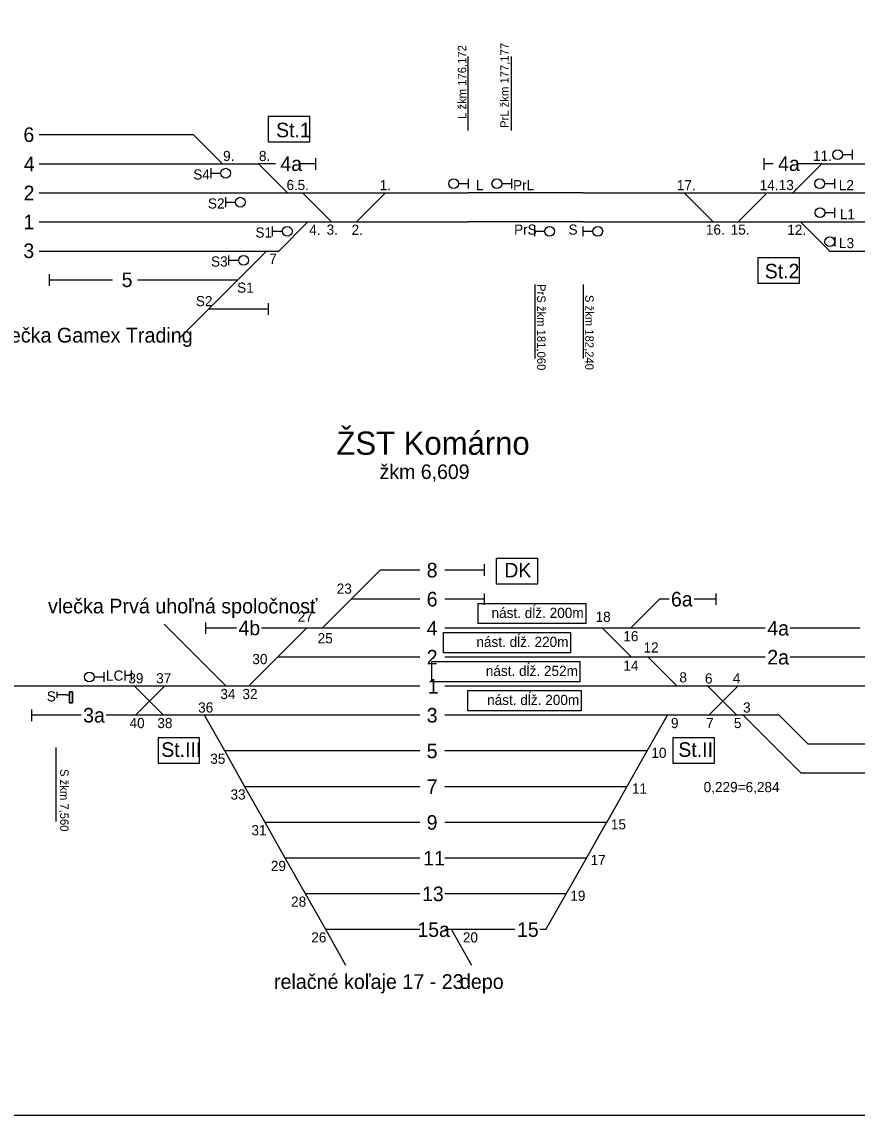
# Model space of a CAD drawing. Extents: x -119 to 851, y -238 to 59.
# Drawn here: x 333.1 to 390.6, y -238 to -162.7 of the extents above; entities that cross this region are included whole.
import ezdxf

# ---------------------------------------------------------------- set-up
doc = ezdxf.new("R2010")
doc.units = 0
for name, color, linetype in [('2', 7, 'Continuous'), ('budova', 7, 'Continuous'), ('Default', 7, 'Continuous'), ('Level 2', 7, 'Continuous'), ('nastupistia', 7, 'Continuous'), ('netlač', 7, 'Continuous'), ('popisky navestidla', 7, 'Continuous'), ('popisky stanic a zastavok', 7, 'Continuous'), ('PU_navestidla', 7, 'Continuous'), ('PU_oznacenie navestidiel', 7, 'Continuous'), ('PU_stan_kolaje', 7, 'Continuous'), ('PU_vlecky', 7, 'Continuous')]:
    doc.layers.add(name, color=color, linetype=linetype)

msp = doc.modelspace()

# ---------------------------------------------------------------- linework, layer by layer
at = {"layer": '2'}
for p, q in [((335.501, -209.067), (335.501, -208.855)), ((335.501, -209.278), (335.501, -209.067)), ((336.123, -209.067), (335.501, -209.067))]:
    msp.add_line(p, q, dxfattribs=at)
for points in [[(336.569, -208.864), (336.359, -208.864), (336.359, -209.61), (336.569, -209.61)], [(336.569, -208.87), (336.359, -208.87), (336.359, -209.61), (336.569, -209.61)]]:
    msp.add_lwpolyline(points, close=True, dxfattribs=at)
at = {"layer": 'budova'}
for points in [[(350.05, -170.981), (352.917, -170.981), (352.917, -169.232), (350.05, -169.232)], [(383.798, -180.699), (386.665, -180.699), (386.665, -178.951), (383.798, -178.951)], [(368.632, -199.668), (365.765, -199.668), (365.765, -201.417), (368.632, -201.417)], [(345.329, -212.023), (342.462, -212.023), (342.462, -213.771), (345.329, -213.771)], [(380.798, -212.023), (377.931, -212.023), (377.931, -213.771), (380.798, -213.771)]]:
    msp.add_lwpolyline(points, close=True, dxfattribs=at)
at = {"layer": 'Default'}
for p, q in [((336.359, -209.61), (336.359, -208.864)), ((336.569, -208.864), (336.569, -209.61)), ((336.569, -209.61), (336.359, -209.61))]:
    msp.add_line(p, q, dxfattribs=at)
msp.add_lwpolyline([(336.123, -209.067), (336.359, -209.067)], dxfattribs=at)
at = {"layer": 'Level 2'}
for p, q in [((344.908, -170.496), (334.273, -170.496)), ((353.342, -172.894), (353.342, -172.095)), ((384.219, -172.894), (384.219, -172.095)), ((334.273, -172.495), (349.377, -172.495)), ((350.55, -172.495), (349.377, -172.495)), ((353.342, -172.495), (352.274, -172.495)), ((384.846, -172.495), (384.219, -172.495)), ((388.2, -172.495), (386.57, -172.495)), ((388.2, -172.495), (409.052, -172.495)), ((334.273, -174.494), (341.172, -174.494)), ((341.172, -174.494), (363.841, -174.494)), ((371.756, -174.494), (377.88, -174.494)), ((377.88, -174.494), (394.077, -174.494)), ((334.273, -176.493), (342.172, -176.493)), ((342.172, -176.493), (360.47, -176.493)), ((360.47, -176.493), (363.841, -176.493)), ((371.756, -176.493), (392.877, -176.493)), ((334.273, -178.492), (350.775, -178.492)), ((388.728, -178.492), (409.052, -178.492)), ((334.986, -180.89), (334.986, -180.091)), ((339.326, -180.491), (334.986, -180.491)), ((347.946, -180.491), (341.049, -180.491)), ((350.081, -182.889), (350.081, -182.09)), ((350.081, -182.49), (345.947, -182.49)), ((364.932, -200.071), (364.932, -200.871)), ((360.51, -200.471), (357.772, -200.471)), ((364.932, -200.471), (362.234, -200.471)), ((360.51, -202.47), (355.773, -202.47)), ((364.932, -202.47), (362.234, -202.47)), ((364.932, -202.07), (364.932, -202.87)), ((377.691, -202.47), (377.013, -202.47)), ((380.887, -202.47), (379.415, -202.47)), ((380.887, -202.07), (380.887, -202.87)), ((345.723, -204.069), (345.723, -204.869)), ((347.864, -204.469), (345.723, -204.469)), ((354.804, -204.469), (349.588, -204.469)), ((360.51, -204.469), (352.688, -204.469)), ((384.302, -204.469), (373.094, -204.469)), ((390.834, -204.469), (386.025, -204.469)), ((360.51, -206.468), (350.689, -206.468)), ((376.239, -206.468), (362.234, -206.468)), ((384.302, -206.468), (376.239, -206.468)), ((392.833, -206.468), (386.025, -206.468)), ((360.51, -208.467), (281.352, -208.467)), ((405.253, -208.467), (362.234, -208.467)), ((333.747, -210.064), (333.747, -210.864)), ((337.159, -210.464), (333.747, -210.464)), ((342.828, -210.464), (338.882, -210.464)), ((360.51, -210.466), (342.83, -210.466)), ((385.268, -210.466), (362.234, -210.466)), ((360.51, -212.925), (347.055, -212.925)), ((376.165, -212.925), (362.234, -212.925)), ((424.601, -212.465), (387.267, -212.465)), ((404.28, -214.464), (386.776, -214.464)), ((360.51, -215.386), (348.447, -215.386)), ((374.769, -215.386), (362.234, -215.386)), ((360.51, -217.847), (349.838, -217.847)), ((373.373, -217.847), (362.234, -217.847)), ((360.51, -220.308), (351.23, -220.308)), ((371.977, -220.308), (362.234, -220.308)), ((360.51, -222.769), (352.621, -222.769)), ((370.581, -222.769), (362.234, -222.769)), ((360.51, -225.23), (354.013, -225.23)), ((362.688, -225.23), (362.234, -225.23)), ((367.056, -225.23), (362.688, -225.23)), ((369.19, -225.23), (368.779, -225.23))]:
    msp.add_line(p, q, dxfattribs=at)
at = {"layer": 'nastupistia'}
for points in [[(371.93, -204.157), (364.516, -204.157), (364.516, -202.772), (371.93, -202.772)], [(370.886, -206.156), (362.127, -206.156), (362.127, -204.771), (370.886, -204.771)], [(371.535, -208.155), (361.33, -208.155), (361.33, -206.77), (371.535, -206.77)], [(371.626, -210.154), (363.819, -210.154), (363.819, -208.769), (371.626, -208.769)]]:
    msp.add_lwpolyline(points, close=True, dxfattribs=at)
at = {"layer": 'netlač'}
for p, q in [((371.756, -174.494), (363.841, -174.494)), ((371.756, -176.493), (363.841, -176.493)), ((373.094, -204.469), (362.234, -204.469))]:
    msp.add_line(p, q, dxfattribs=at)
at = {"layer": 'popisky navestidla'}
for p, q in [((363.841, -170.181), (363.841, -165.091)), ((366.815, -170.181), (366.815, -165.091)), ((368.428, -180.806), (368.428, -185.897)), ((371.756, -180.806), (371.756, -185.897)), ((335.452, -217.779), (335.452, -212.688))]:
    msp.add_line(p, q, dxfattribs=at)
msp.add_lwpolyline([(-118.951, -238.008), (851.049, -238.008), (851.049, 58.992), (-118.951, 58.992)], close=True, dxfattribs=at)
at = {"layer": 'PU_navestidla'}
for p, q in [((390.295, -171.524), (390.295, -172.196)), ((390.295, -171.861), (389.623, -171.861)), ((346.118, -173.466), (346.118, -172.795)), ((346.118, -173.129), (346.79, -173.129)), ((363.841, -173.859), (363.169, -173.859)), ((363.841, -173.522), (363.841, -174.194)), ((366.815, -173.859), (366.143, -173.859)), ((366.815, -173.522), (366.815, -174.194)), ((389.067, -173.859), (388.395, -173.859)), ((389.067, -173.522), (389.067, -174.194)), ((347.13, -175.465), (347.13, -174.794)), ((347.13, -175.128), (347.802, -175.128)), ((389.084, -175.858), (388.412, -175.858)), ((389.084, -175.521), (389.084, -176.193)), ((350.351, -177.464), (350.351, -176.793)), ((368.428, -177.466), (368.428, -176.794)), ((371.756, -177.466), (371.756, -176.794)), ((350.351, -177.127), (351.023, -177.127)), ((368.428, -177.129), (369.1, -177.129)), ((371.756, -177.129), (372.428, -177.129)), ((389.087, -177.52), (389.087, -178.192)), ((347.346, -179.463), (347.346, -178.792)), ((347.346, -179.126), (348.018, -179.126)), ((338.732, -207.495), (338.732, -208.167)), ((338.732, -207.832), (338.06, -207.832))]:
    msp.add_line(p, q, dxfattribs=at)
for centre in [(389.287, -171.86), (347.126, -173.131), (362.833, -173.857), (365.807, -173.857), (388.059, -173.857), (348.138, -175.13), (388.076, -175.856), (351.359, -177.129), (369.436, -177.13), (372.764, -177.13), (388.751, -177.856), (348.354, -179.128), (337.724, -207.831)]:
    msp.add_circle(centre, 0.336, dxfattribs=at)
at = {"layer": 'PU_stan_kolaje'}
for p, q in [((347.946, -180.491), (343.912, -184.525)), ((347.153, -208.467), (342.879, -204.194))]:
    msp.add_line(p, q, dxfattribs=at)
for points in [[(344.908, -170.496), (346.907, -172.495)], [(349.377, -172.495), (351.376, -174.494)], [(388.2, -172.495), (386.201, -174.494)], [(352.42, -174.494), (354.419, -176.493)], [(358.13, -174.494), (356.131, -176.493)], [(378.715, -174.494), (380.714, -176.493)], [(384.424, -174.494), (382.425, -176.493)], [(352.774, -176.493), (350.775, -178.492)], [(386.729, -176.493), (388.726, -178.49)], [(349.945, -178.492), (347.946, -180.491)], [(355.773, -202.47), (357.772, -200.471)], [(353.774, -204.469), (355.773, -202.47)], [(375.014, -204.469), (377.013, -202.47)], [(350.689, -206.468), (352.688, -204.469)], [(375.093, -206.468), (373.094, -204.469)], [(348.69, -208.467), (350.689, -206.468)], [(378.238, -208.467), (376.239, -206.468)], [(342.83, -210.466), (340.831, -208.467)], [(340.912, -210.466), (342.911, -208.467)], [(382.338, -210.466), (380.339, -208.467)], [(380.42, -210.466), (382.419, -208.467)], [(347.055, -212.925), (345.664, -210.464)], [(376.169, -212.927), (377.56, -210.466)], [(384.777, -212.465), (382.778, -210.466)], [(387.267, -212.465), (385.268, -210.466)], [(348.447, -215.386), (347.055, -212.925)], [(374.773, -215.388), (376.164, -212.927)], [(386.776, -214.464), (384.777, -212.465)], [(349.838, -217.847), (348.447, -215.386)], [(373.377, -217.849), (374.768, -215.388)], [(351.23, -220.308), (349.838, -217.847)], [(371.981, -220.31), (373.372, -217.849)], [(352.621, -222.769), (351.23, -220.308)], [(370.585, -222.77), (371.976, -220.31)], [(354.013, -225.23), (352.621, -222.769)], [(369.189, -225.231), (370.58, -222.77)], [(355.404, -227.691), (354.013, -225.23)], [(364.079, -227.691), (362.688, -225.23)]]:
    msp.add_lwpolyline(points, dxfattribs=at)

# ---------------------------------------------------------------- texts
at = {"layer": 'budova'}
for s, p in [('St.1', (350.595, -170.659)), ('St.2', (384.267, -180.378)), ('DK', (366.32, -200.977)), ('St.III', (342.682, -213.331)), ('St.II', (378.311, -213.331))]:
    msp.add_text(s, height=1.0044, dxfattribs=at).set_placement(p)
at = {"layer": 'nastupistia'}
for s, p in [('nást. dĺž. 200m', (365.44, -203.763)), ('nást. dĺž. 220m', (364.396, -205.762)), ('nást. dĺž. 252m', (365.046, -207.761)), ('nást. dĺž. 200m', (365.136, -209.76))]:
    msp.add_text(s, height=0.7, dxfattribs=at).set_placement(p)
at = {"layer": 'popisky navestidla'}
for s, rotation, p in [('L žkm 176,172', 90, (363.699, -169.393)), ('PrL žkm 177,177 ', 90, (366.623, -170.015)), ('PrS žkm 181,060 ', 270, (368.584, -180.767)), ('S žkm 182,240', 270, (371.896, -181.516)), ('S žkm 7,560', 270, (335.716, -214.17))]:
    msp.add_text(s, height=0.57931, rotation=rotation, dxfattribs=at).set_placement(p)
at = {"layer": 'popisky stanic a zastavok'}
for s, height, p in [('ŽST Komárno', 1.6, (354.754, -192.527)), ('žkm 6,609', 1.0044, (357.73, -194.195))]:
    msp.add_text(s, height=height, dxfattribs=at).set_placement(p)
at = {"layer": 'PU_oznacenie navestidiel'}
for s, p in [('9.', (346.944, -172.297)), ('8.', (349.414, -172.297)), ('11.', (387.593, -172.285)), ('S4', (344.886, -173.566)), ('6.', (351.316, -174.296)), ('5.', (352.077, -174.296)), ('1.', (357.733, -174.307)), ('L', (364.359, -174.307)), ('PrL', (366.928, -174.307)), ('17.', (378.211, -174.307)), ('14.', (383.92, -174.307)), ('13.', (385.228, -174.296)), ('L2', (389.368, -174.307)), ('S2', (345.899, -175.565)), ('L1', (389.438, -176.306)), ('S1', (349.173, -177.564)), ('4.', (352.879, -177.379)), ('3.', (354.076, -177.367)), ('2.', (355.797, -177.379)), ('PrS', (366.993, -177.368)), ('S', (370.747, -177.368)), ('16.', (380.21, -177.367)), ('15.', (381.921, -177.367)), ('12.', (385.816, -177.379)), ('L3', (389.385, -178.294)), ('S3', (346.113, -179.563)), ('7', (350.118, -179.378)), ('S1', (347.908, -181.365)), ('S2', (345.064, -182.292)), ('23', (354.774, -202.095)), ('27', (352.089, -204.024)), ('18', (372.61, -204.036)), ('25', (353.459, -205.511)), ('16', (374.521, -205.374)), ('12', (375.915, -206.15)), ('30', (348.959, -206.946)), ('14', (374.521, -207.4)), ('LCH', (338.875, -208.084)), ('39', (340.414, -208.269)), ('37', (342.333, -208.269)), ('8', (378.384, -208.207)), ('6', (380.147, -208.281)), ('4', (382.065, -208.269)), ('S', (334.793, -209.515)), ('34', (346.755, -209.353)), ('32', (348.277, -209.353)), ('36', (345.223, -210.28)), ('3', (382.772, -210.28)), ('40', (340.496, -211.352)), ('38', (342.413, -211.352)), ('9', (377.805, -211.352)), ('7', (380.227, -211.352)), ('5', (382.143, -211.352)), ('10', (376.453, -213.405)), ('35', (346.06, -213.811)), ('11', (375.112, -215.864)), ('0,229=6,284', (380.058, -215.763)), ('33', (347.454, -216.272)), ('31', (348.9, -218.733)), ('15', (373.663, -218.326)), ('29', (350.235, -221.194)), ('17', (372.265, -220.786)), ('19', (370.868, -223.247)), ('28', (351.627, -223.655)), ('26', (353.019, -226.116)), ('20', (363.463, -226.116))]:
    msp.add_text(s, height=0.7, dxfattribs=at).set_placement(p)
at = {"layer": 'PU_stan_kolaje'}
for s, height, p in [('6', 1.004, (333.184, -170.981)), ('4', 1.004, (333.213, -172.997)), ('4a', 1.0044, (350.891, -172.98)), ('4a', 1.0044, (385.187, -172.98)), ('2', 1.004, (333.197, -174.996)), ('1', 1.004, (333.182, -176.995)), ('3', 1.004, (333.18, -178.977)), ('5', 1.004, (339.953, -180.976)), ('8', 1.004, (360.971, -200.973)), ('6', 1.004, (360.973, -202.972)), ('6a', 1.0044, (377.804, -202.972)), ('4b', 1.0044, (348.004, -204.954)), ('4', 1.004, (360.974, -204.971)), ('4a', 1.0044, (384.442, -204.971)), ('2', 1.004, (360.976, -206.97)), ('2a', 1.0044, (384.442, -206.97)), ('1', 1.004, (361.052, -208.969)), ('3a', 1.0044, (337.299, -210.966)), ('3', 1.004, (360.973, -210.968)), ('5', 1.004, (360.969, -213.427)), ('7', 1.004, (360.973, -215.888)), ('9', 1.004, (360.971, -218.349)), ('11', 1.0044, (360.732, -220.81)), ('13', 1.0044, (360.653, -223.271)), ('15a', 1.0044, (360.331, -225.732)), ('15', 1.0044, (367.195, -225.732))]:
    msp.add_text(s, height=height, dxfattribs=at).set_placement(p)
at = {"layer": 'PU_vlecky'}
for s, p in [('vlečka Gamex Trading', (331.27, -184.796)), ('vlečka Prvá uhoľná spoločnosť', (334.88, -203.451)), ('relačné koľaje 17 - 23', (350.448, -229.317)), ('depo', (363.26, -229.317))]:
    msp.add_text(s, height=1.015, dxfattribs=at).set_placement(p)

doc.saveas('drawing.dxf')
